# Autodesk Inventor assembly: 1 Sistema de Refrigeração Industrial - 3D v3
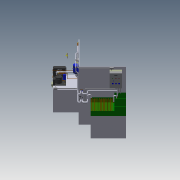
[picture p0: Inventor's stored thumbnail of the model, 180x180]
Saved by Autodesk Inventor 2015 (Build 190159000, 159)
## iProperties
Created: 2015-06
Part Number: 1 Sistema de Refrigeração Industrial - 3D v3
Document SubType Name: Assembly
Designer: Franzi-CAD
Translation Standard: IGES 5.3
FileName: 1 Sistema de RefrigeraÃ§Ã£o Industrial - 3D v3
PreProcessor: AutoCAD 2015 - English
PostProcessor: Build: 160, Release: 2012 RTM - Date: Tue 03/01/2011
Sent Units: millimeter
Uncertainty: 0.01
Author: Franzi-CAD
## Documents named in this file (5)
- C:\Users\Renato\Desktop\Refrigeração\1 Sistema de Refrigeração Industrial - 3D v3.iam
- C:\Users\Renato\Desktop\Refrigeração\serpentina.iam
- C:\Users\Renato\Desktop\Refrigeração\VÃ¡lvula GBC.ipt
- C:\Users\Renato\Desktop\Refrigeração\_U1.iam
- C:\Users\Renato\Desktop\Refrigeração\1 Sistema de Refrigeração Industrial - 3D v3.ipt
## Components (4 placed, 4 different names)
1. serpentina:1 [sub-assembly] — Mate:1, Mate:2
2. VÃ¡lvula GBC:1
3. _U1:1 [sub-assembly]
4. NonBlockGeom — Mate:1, Mate:2
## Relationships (2: Mate 2)
- Mate:1: serpentina:1 ↔ NonBlockGeom
- Mate:2: serpentina:1 ↔ NonBlockGeom
